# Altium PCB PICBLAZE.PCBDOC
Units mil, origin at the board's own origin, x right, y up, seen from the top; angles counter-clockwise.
Board outline 6000 x 4000 mil, 2 copper layers (Top Layer, Bottom Layer); 32 components, 76 nets, 253 pads, 144 vias.
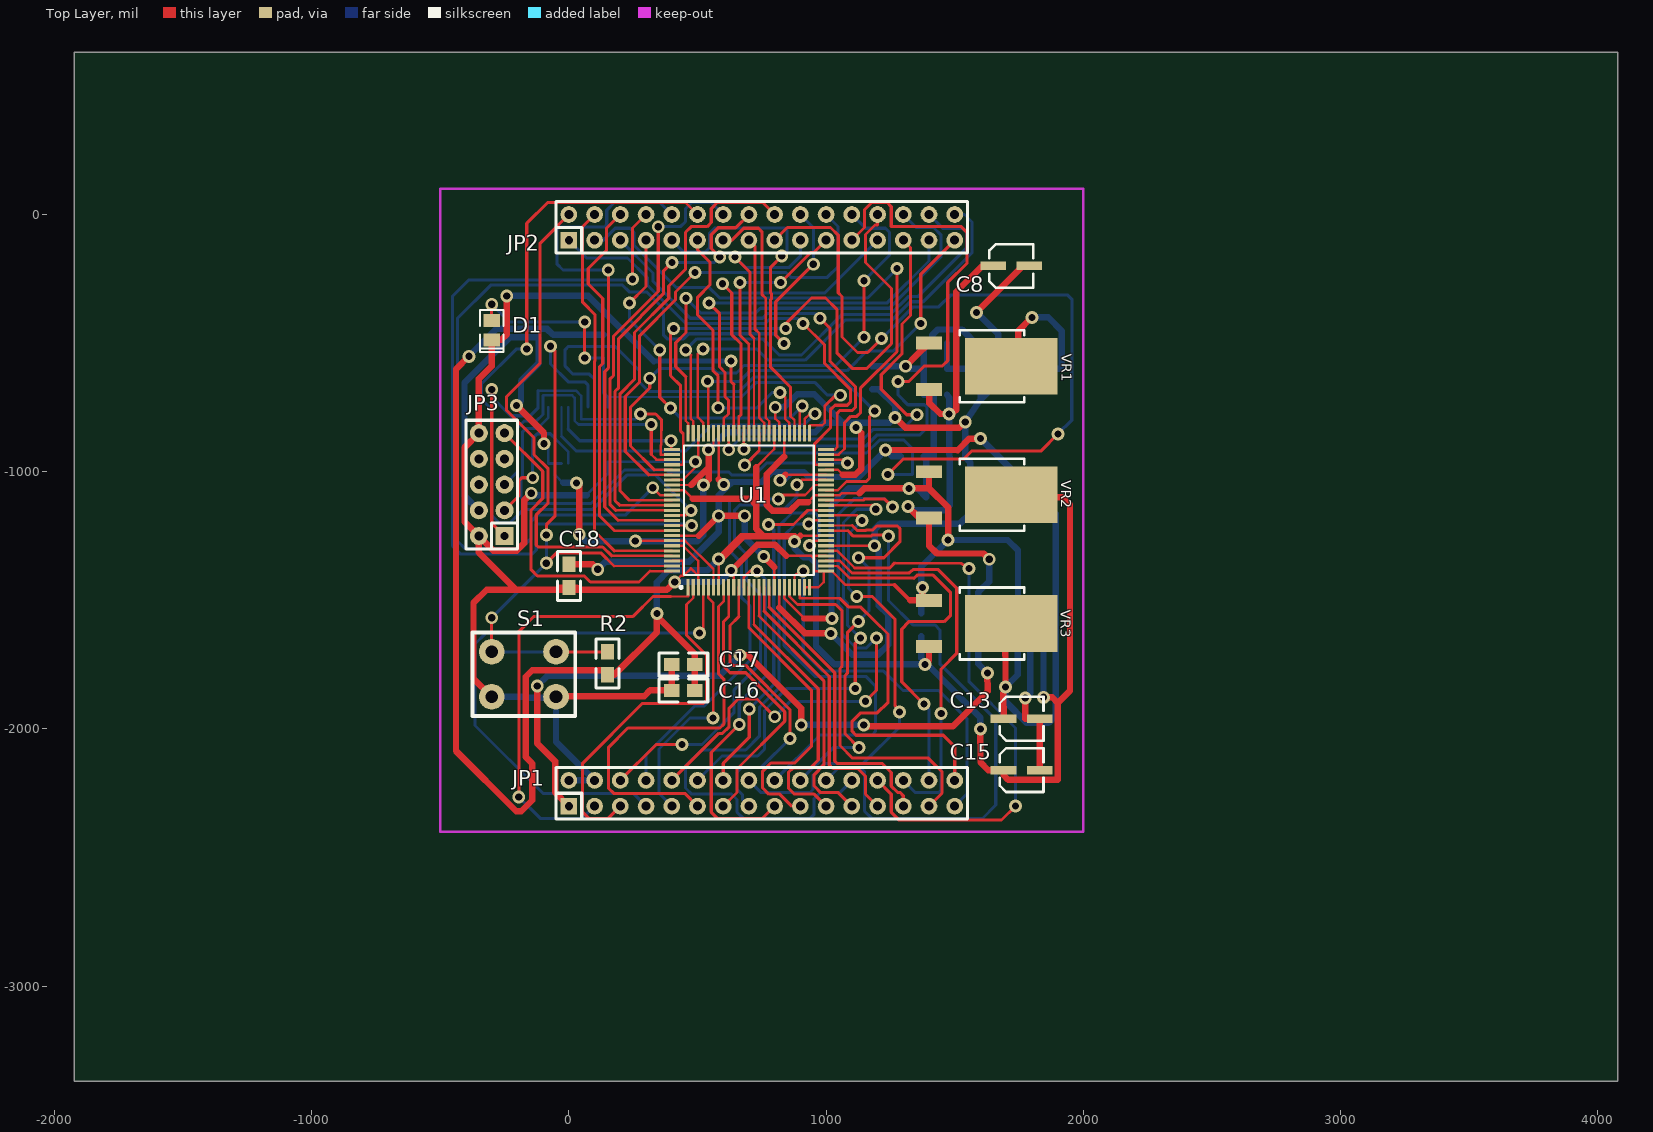
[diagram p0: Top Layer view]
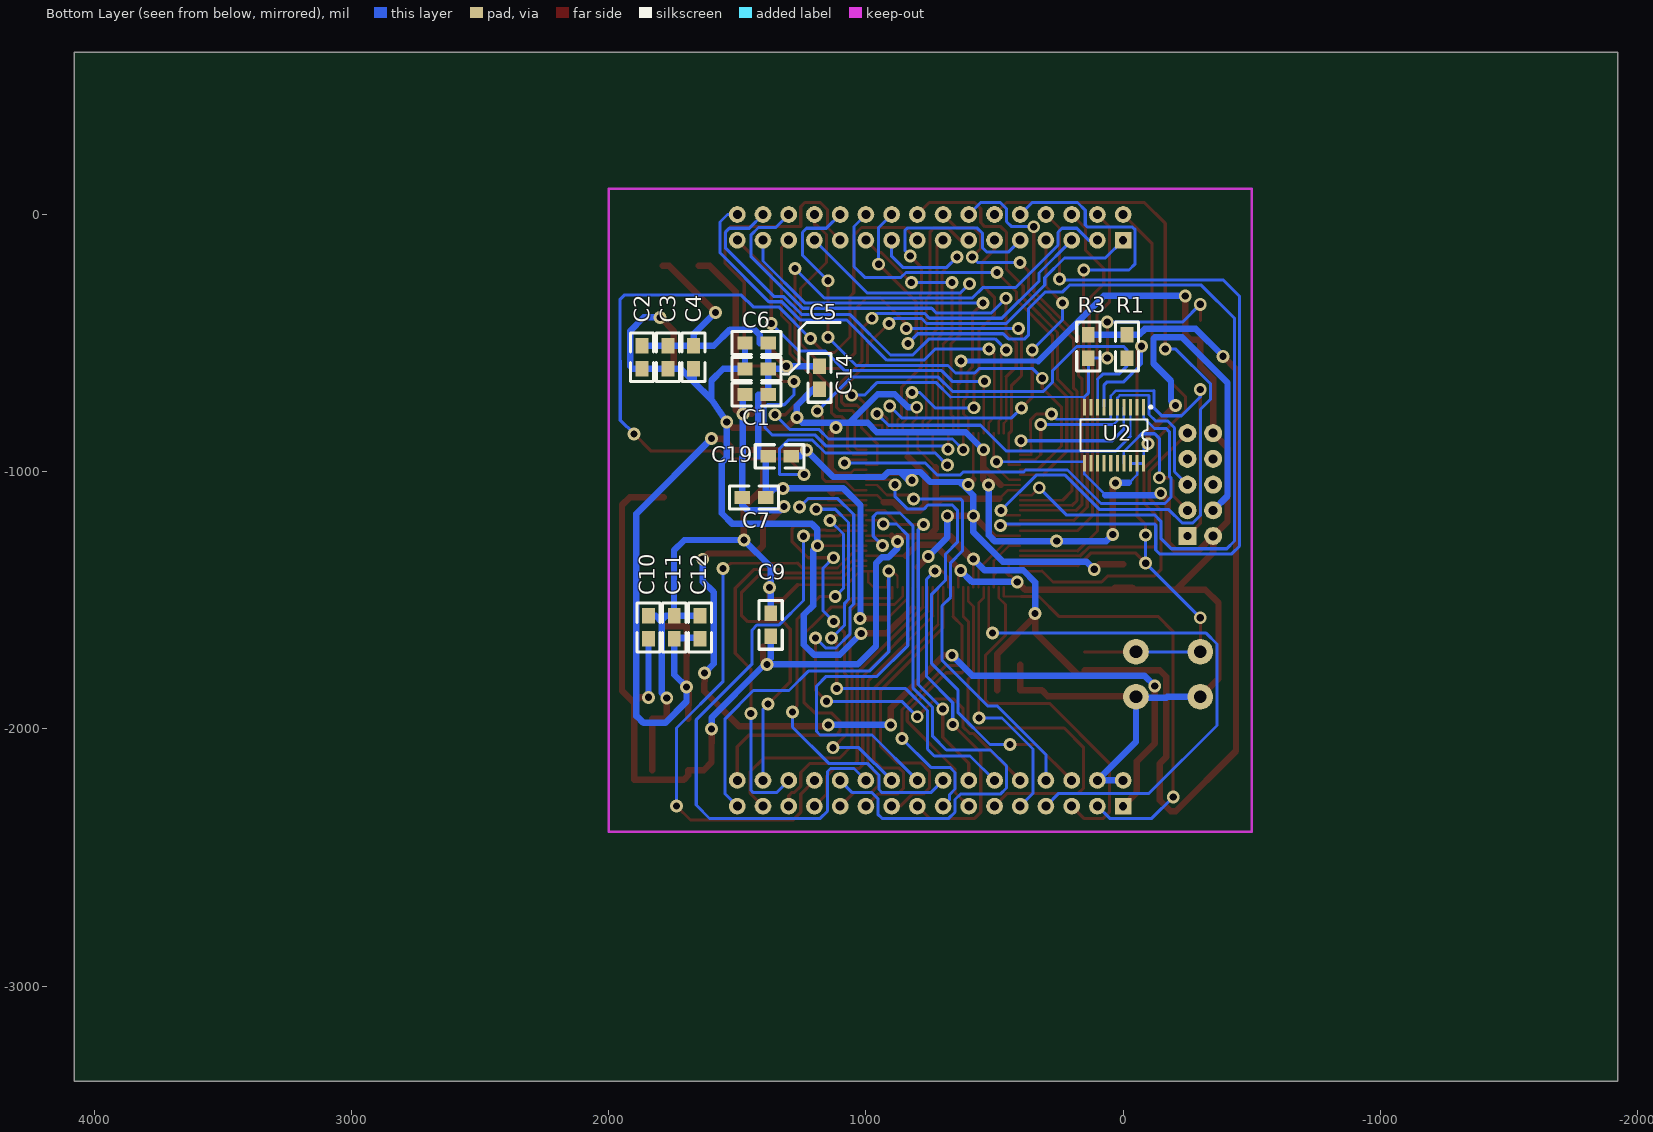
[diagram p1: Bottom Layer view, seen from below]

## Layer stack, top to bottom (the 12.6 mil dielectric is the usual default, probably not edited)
Top Layer: signal copper 1.4
Dielectric: dielectric 12.6, FR-4, Dk 4.8
Bottom Layer: signal copper 1.4

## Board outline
-1922.68,-3369.45 4077.32,-3369.45 4077.32,630.55 -1922.68,630.55

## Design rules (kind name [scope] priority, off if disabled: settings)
Clearance Clearance_1 [InComponent('U1') Or InComponent('U2')] p1: gap=7
Clearance [All] p2: gap=8
ComponentClearance [All] p1: gap=10 collisioncheckmode=0
FanoutControl Fanout_BGA [IsBGA] p1: bgadir=Out bgaviamode=Centered fanoutstyle=Auto fanoutdirection=InThenOut viagrid=1 // Fanout_BGA (Default Rule)
FanoutControl Fanout_LCC [IsLCC] p2: bgadir=Out bgaviamode=Centered fanoutstyle=Auto fanoutdirection=InThenOut viagrid=1 // Fanout_LCC (Default Rule)
FanoutControl Fanout_SOIC [IsSOIC] p3: bgadir=Out bgaviamode=Centered fanoutstyle=Auto fanoutdirection=InThenOut viagrid=1 // Fanout_SOIC (Default Rule)
FanoutControl Fanout_Small [(CompPinCount < 5)] p4: bgadir=Out bgaviamode=Centered fanoutstyle=Auto fanoutdirection=InThenOut viagrid=1 // Fanout_Small (Default Rule)
FanoutControl Fanout_Default [All] p5: bgadir=Out bgaviamode=Centered fanoutstyle=Auto fanoutdirection=InThenOut viagrid=1 // Fanout_Default (Default Rule)
PolygonConnect [All] p1: connectstyle=Relief reliefconductorwidth=10 reliefentries=4 polygonreliefangle="90 Angle"
RoutingLayers [All] p1: top layer_v5=FALSE bottom layer_v5=FALSE
RoutingVias [All] p1: holewidth=28 width=50 viastyle="Through Hole" minholewidth=28 minwidth=50 maxholewidth=28 maxwidth=50
SMDNeckDown [All] p1: percent=80.000
SolderMaskExpansion [All] p1: expansion=4
TestPointUsage [All] p1: valid=0 allowmultiple=FALSE
Testpoint [All] p1: side=15 testpointundercomponent=TRUE minsize=40 maxsize=100 preferedsize=60 minholesize=0 maxholesize=40 preferedholesize=32 testpointgrid=1 style=1023 order=1234567890
Width Width_1 [InNet('+1,2V') Or InNet('+2,5V') Or InNet('+3,3V') Or InNet('+5V') Or InNet('GND')] p1: maxlimit=25 minlimit=10 preferedwidth=25
Width [All] p2: maxlimit=12 minlimit=10 preferedwidth=12
11 further rules are at their usual default settings.

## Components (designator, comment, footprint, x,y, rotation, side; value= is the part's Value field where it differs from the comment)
C1 "Cap" 0805 1380,-700 r0 bottom
C2 "Cap" 0805 1870,-600 r90 bottom
C3 "Cap" 0805 1770,-600 r90 bottom
C4 "Cap" 0805 1670,-600 r90 bottom
C5 "Cap" 0805 1470,-600 r180 bottom
C6 "Cap Pol3" 0805 1470,-500 r180 bottom
C7 "Cap" 0805 1480,-1100 r180 bottom
C8 "Cap Pol3" CE1SMD4X5.4 1650,-200 r0 top
C9 "Cap" 0805 1370,-1550 r270 bottom
C10 "Cap" 0805 1845,-1650 r90 bottom
C11 "Cap" 0805 1745,-1650 r90 bottom
C12 "Cap" 0805 1645,-1650 r90 bottom
C13 "Cap Pol3" CE1SMD4X5.4 1690,-1960 r0 top
C14 "Cap" 0805 1180,-680 r90 bottom
C15 "Cap Pol3" CE1SMD4X5.4 1690,-2160 r0 top
C16 "Cap" 0805 400,-1850 r0 top
C17 "Cap" 0805 400,-1750 r0 top
C18 "Cap" 0805 0,-1450 r90 top
C19 "Cap" 0805 1380,-940 r180 bottom
D1 "LED3" "SMD _LED" -300,-450 r90 top
JP1 "Header 16X2" IDC-32_65mils 0,-2300 r0 top
JP2 "Header 16X2" IDC-32_65mils 0,-100 r0 top
JP3 "JTAG" IDC-10 -850,-1650 r90 top
R1 "Res2" 0805 -14.66,-558.08 r90 bottom
R2 "Res2" 0805 150,-1700 r270 top
R3 "Res2" 0805 135.34,-558.08 r90 bottom
S1 "SW-PB" U_SW -50,-1700 r270 top
U1 "XC3S200-4VQ100C" VQ100 700,-1150 r90 top
U2 "XCF01SVO20C" VO20 35.34,-858.08 r0 bottom
VR1 "Comment" TO252_mod 1400,-500 r270 top
VR2 "Comment" TO252_mod 1400,-1000 r270 top
VR3 "Comment" TO252_mod 1400,-1500 r270 top locked

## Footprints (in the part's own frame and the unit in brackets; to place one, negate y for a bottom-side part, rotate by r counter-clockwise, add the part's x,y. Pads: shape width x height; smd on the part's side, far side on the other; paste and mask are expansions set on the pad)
0805 [mil]
  rect 60x50 smd: 1(0,0) 2(90,0)
  silkscreen extent -50,-45 140,45
CE1SMD4X5.4 [mil]
  rect 100x33 smd: 1(0,0) 2(140,0)
  silkscreen extent -15,-85 155,85
IDC-10 [mil]
  rect 70x70 hole 32: 1(400,-600)
  round 70 hole 35: 2(400,-500) 3(500,-600) 4(500,-500) 5(600,-600) 6(600,-500) 7(700,-600) 8(700,-500) 9(800,-600) 10(800,-500)
  silkscreen extent 350,-650 850,-450
IDC-32_65mils [mil]
  rect 65x65 hole 32: 1(0,0)
  round 65 hole 35: 2(0,100) 3(100,0) 4(100,100) 5(200,0) 6(200,100) 7(300,0) 8(300,100) 9(400,0) 10(400,100) 11(500,0) 12(500,100) 13(600,0) 14(600,100) 15(700,0) 16(700,100) 17(800,0) 18(800,100) 19(900,0) 20(900,100) 21(1000,0) 22(1000,100) 23(1100,0) 24(1100,100) 25(1200,0) 26(1200,100) 27(1300,0) 28(1300,100) 29(1400,0) 30(1400,100) 31(1500,0) 32(1500,100)
  silkscreen extent -50,-50 1550,150
"SMD _LED" [mm]
  rect 1.3x1.6 smd: 1(0.95,0) 2(-0.95,0)
  silkscreen extent -2.13,-1.15 2,1.15
TO252_mod [mil]
  rect 50x100 smd: 1(0,0) 3(180,0)
  rect 220x360 smd: 2(90,320)
  silkscreen extent -50,120 230,370
U_SW [mil]
  round 100 hole 50: 1(175,0) 1(175,-250) 2(0,0) 2(0,-250)
  silkscreen extent -75,-325 250,75
VO20 [mm]
  rect 0.3x1.65 smd: 1(-2.925,-2.775) 2(-2.275,-2.775) 3(-1.625,-2.775) 4(-0.975,-2.775) 5(-0.325,-2.775) 6(0.325,-2.775) 7(0.975,-2.775) 8(1.625,-2.775) 9(2.275,-2.775) 10(2.925,-2.775) 11(2.925,2.775) 12(2.275,2.775) 13(1.625,2.775) 14(0.975,2.775) 15(0.325,2.775) 16(-0.325,2.775) 17(-0.975,2.775) 18(-1.625,2.775) 19(-2.275,2.775) 20(-2.925,2.775)
  silkscreen extent -3.75,-2.9 3.3,1.55
VQ100 [mm]
  rect 1.6x0.3 smd: 1(-7.6,6) 2(-7.6,5.5) 3(-7.6,5) 4(-7.6,4.5) 5(-7.6,4) 6(-7.6,3.5) 7(-7.6,3) 8(-7.6,2.5) 9(-7.6,2) 10(-7.6,1.5) 11(-7.6,1) 12(-7.6,0.5) 13(-7.6,0) 14(-7.6,-0.5) 15(-7.6,-1) 16(-7.6,-1.5) 17(-7.6,-2) 18(-7.6,-2.5) 19(-7.6,-3) 20(-7.6,-3.5) 21(-7.6,-4) 22(-7.6,-4.5) 23(-7.6,-5) 24(-7.6,-5.5) 25(-7.6,-6) 51(7.6,-6) 52(7.6,-5.5) 53(7.6,-5) 54(7.6,-4.5) 55(7.6,-4) 56(7.6,-3.5) 57(7.6,-3) 58(7.6,-2.5) 59(7.6,-2) 60(7.6,-1.5) 61(7.6,-1) 62(7.6,-0.5) 63(7.6,0) 64(7.6,0.5) 65(7.6,1) 66(7.6,1.5) 67(7.6,2) 68(7.6,2.5) 69(7.6,3) 70(7.6,3.5) 71(7.6,4) 72(7.6,4.5) 73(7.6,5) 74(7.6,5.5) 75(7.6,6)
  rect 0.3x1.6 smd: 26(-6,-7.6) 27(-5.5,-7.6) 28(-5,-7.6) 29(-4.5,-7.6) 30(-4,-7.6) 31(-3.5,-7.6) 32(-3,-7.6) 33(-2.5,-7.6) 34(-2,-7.6) 35(-1.5,-7.6) 36(-1,-7.6) 37(-0.5,-7.6) 38(0,-7.6) 39(0.5,-7.6) 40(1,-7.6) 41(1.5,-7.6) 42(2,-7.6) 43(2.5,-7.6) 44(3,-7.6) 45(3.5,-7.6) 46(4,-7.6) 47(4.5,-7.6) 48(5,-7.6) 49(5.5,-7.6) 50(6,-7.6) 76(6,7.6) 77(5.5,7.6) 78(5,7.6) 79(4.5,7.6) 80(4,7.6) 81(3.5,7.6) 82(3,7.6) 83(2.5,7.6) 84(2,7.6) 85(1.5,7.6) 86(1,7.6) 87(0.5,7.6) 88(0,7.6) 89(-0.5,7.6) 90(-1,7.6) 91(-1.5,7.6) 92(-2,7.6) 93(-2.5,7.6) 94(-3,7.6) 95(-3.5,7.6) 96(-4,7.6) 97(-4.5,7.6) 98(-5,7.6) 99(-5.5,7.6) 100(-6,7.6)
  silkscreen extent -7.72,-6.4 6.4,6.82

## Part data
C1 C2 C3 C4 C5 C7 C9 C10 C11 C12 C14 C16 C17 C18 C19: "Capacitor"
C6 C8 C13 C15: "Polarized Capacitor (Surface Mount)"
D1: "Typical BLUE SiC LED"
JP1 JP2: "Header, 16-Pin, Dual row"
JP3: library part "Header 5X2", "Header, 5-Pin, Dual row"
R1 R2 R3: "Resistor"
S1: "Switch"
U1: "Spartan-3 1.2V FPGA, 63 User I/Os, 100-pin VQFP, Standard Performance, Commercial Grade"
U2: "XCF00S Series, Platform Flash In-System Programmable Configuration 3.3V PROM, 20-Pin TSOP, 1-Megabit, Commercial Grade"

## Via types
v1: diameter 50, hole 28, Top Layer to Bottom Layer, 144 vias

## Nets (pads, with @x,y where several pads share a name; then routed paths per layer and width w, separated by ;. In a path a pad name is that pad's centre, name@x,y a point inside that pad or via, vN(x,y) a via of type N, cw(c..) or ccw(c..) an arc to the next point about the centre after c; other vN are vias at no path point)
+1,2V: C11.1 C12.1 C13.1 C18.2 C19.2 U1.18 U1.45 U1.69 U1.93 VR3.2 | length 5481.7
  Top Layer w9.45: U1.93 505.35,-1248.42 ; 581.89,-1029.52 U1.69 ; U1.18 798.42,-1370.55 ; 842.07,-1012.2 U1.45
  Top Layer w25: C18.2 92.87,-1360 v1(112.32,-1379.45) ; 505.35,-1248.42 v1(582.32,-1171.45) v1(683.32,-1171.45) ; 581.89,-1029.52 v1(602.32,-1049.95) ; v1(757.32,-1329.45) 798.42,-1370.55 ; v1(821.11,-1033.16) 842.07,-1012.2 ; v1(1231.32,-915.45) 1511.32,-916.45 1556,-871 v1(1600,-871) ; C13.1 1689,-1861 v1(1697.32,-1836.45) 1697,-1600 VR3.2@1786.54,-1600
  Bottom Layer w25: v1(112.32,-1379.45) 142.32,-1349.45 467.3,-1349.45 582.32,-1234.42 v1(582.32,-1171.45) 582.32,-1091.45 613.07,-1060.7 633.82,-1039.95 ; v1(602.32,-1049.95) 612.32,-1039.95 633.82,-1039.95 ; v1(683.32,-1171.45) 683.32,-1255.45 v1(757.32,-1329.45) ; v1(821.11,-1033.16) 827.89,-1039.95 866.89,-1000.95 ; C19.2 1255.87,-940 v1(1231.32,-915.45) 1126.32,-1020.45 932.82,-1020.45 913.32,-1000.95 866.89,-1000.95 ; v1(1600,-871) 1892,-1163 1892,-1951 ; 1891.32,-1949.45 1864.32,-1976.45 1780.32,-1976.45 1697.32,-1893.45 v1(1697.32,-1836.45) 1745,-1789 C11.1 ; 633.82,-1039.95 749.89,-1039.95 788.89,-1000.95 821.11,-1000.95 866.89,-1000.95 ; C11.1 1645,-1645.77 1745,-1645.77 C11.1
+2,5V: C9.2 C10.1 C15.1 C16.2 C17.2 R1.2 R2.2 R3.2 U1.7 U1.33 U1.58 U1.84 VR2.2 VR3.3 | length 9479.3
  Top Layer w9.45: U1.84 448.13,-1071.26 482.32,-1105.45 ; U1.7 v1@581.89,-1349.45 ; 728.82,-981.87 798.43,-912.26 U1.58 ; 899.84,-1248.43 U1.33
  Top Layer w25: v1(-388.68,-551.45) -438.68,-601.45 -438.68,-2085.45 -204.68,-2319.45 -184.68,-2319.45 -142.68,-2277.45 -142.68,-2134.45 -168.18,-2108.95 -168.18,-1796.95 -142.68,-1771.45 150,-1771.45 R2.2 175.77,-1790 342.32,-1623.45 v1(342.32,-1551.45) ; v1@342.32,-1561.77 490,-1709.45 C17.2 C16.2 ; 482.32,-1105.45 704.82,-1105.45 728.82,-1129.45 ; v1@581.89,-1349.45 680.39,-1250.95 ; v1(582.32,-1339.45) 670.82,-1250.95 877.32,-1250.95 v1(877.32,-1270.95) ; 728.82,-981.87 728.82,-1222.45 757.32,-1250.95 ; 857.32,-1250.95 v1(877.32,-1270.95) ; 899.84,-1248.43 v1(877.32,-1270.95) ; v1(1385,-1748.95) 1400,-1733.95 VR3.3 ; v1(1600,-2000) 1600.32,-2116.95 1600.32,-2129.45 1630.87,-2160 C15.1 1690,-2180.12 1707.32,-2197.45 1901.32,-2197.45 1901.32,-1922.45 1901,-1899 ; VR2.2@1786.54,-1100 1918,-1100 1948,-1129 1948,-1852 1901,-1899 ; v1(1845,-1877) 1879,-1877 1901,-1899
  Bottom Layer w25: v1(-388.68,-551.45) -282.18,-444.95 -84.7,-444.95 -61.57,-468.08 R1.2 R3.2 ; v1(342.32,-1551.45) 342.32,-1429.45 388.82,-1382.95 538.82,-1382.95 v1(582.32,-1339.45) ; v1(877.32,-1270.95) 877.32,-1296.95 912.32,-1331.95 937.32,-1331.95 960.82,-1355.45 960.82,-1678.95 1030.82,-1748.95 v1@1393.82,-1748.95 ; C9.2 1370,-1725.13 1412.32,-1767.45 1600,-1956 v1(1600,-2000) ; v1(1845,-1877) C10.1
+3,3V: C2.1 C3.1 C4.1 C5.1 C6.1 C14.1 JP3.4 U1.6 U1.19 U1.31 U1.46 U1.57 U1.70 U1.83 U1.94 U2.18 U2.19 U2.20 VR1.2 | length 8726.3
  Top Layer w9.45: v1@259.66,-1268.11 U1.94 451.98,-1268.11 562.2,-1378.33 U1.6 ; U1.83 475.33,-1051.57 ; v1(543.32,-914.45) 562.2,-895.57 U1.70 ; v1(802.32,-749.45) 802.32,-793.45 818.11,-809.24 U1.57 ; 818.11,-1528.83 U1.19 ; U1.31 v1(1188.32,-1287.8) ; U1.46 1045.6,-992.52 1065.02,-1011.95
  Top Layer w25: v1(-203.68,-742.45) -96.68,-849.45 v1(-96.68,-891.45) ; v1(29.32,-1043.45) 40.32,-1054.45 v1(40.32,-1244.45) ; v1(258.32,-1269.45) v1@259.66,-1268.11 ; 475.33,-1051.57 499.08,-1027.83 543.32,-983.58 ; v1(522.82,-1051.57) 543.32,-1031.07 543.32,-983.58 ; v1(543.32,-914.45) 543.32,-983.58 ; 818.11,-1528.83 917.75,-1628.47 v1(1018.34,-1628.47) ; 1065.02,-1011.95 1113.82,-1011.95 1136.32,-989.45 1136.32,-848.45 v1(1116.32,-828.45) ; v1(1268.32,-789.45) 1308.32,-829.45 1518,-829 v1(1541,-807) ; VR1.2@1747.2,-588.42 1747,-453 v1(1800,-400)
  Bottom Layer w9.45: v1(-96.68,-891.45) -79.82,-908.31 U2.20 ; U2.19 -54.23,-1011.9 -22.68,-1043.45
  Bottom Layer w12: U2.20 U2.19 U2.18
  Bottom Layer w25: JP3.4 -405.68,-1094.32 -405.68,-654.28 -229.35,-477.95 -122.68,-477.95 -118.16,-482.46 -118.16,-579.56 -186.18,-647.58 -186.18,-724.95 v1(-203.68,-742.45) ; -22.68,-1043.45 v1(29.32,-1043.45) ; v1(40.32,-1244.45) 65.32,-1269.45 v1(258.32,-1269.45) 499.65,-1269.45 522.82,-1246.28 v1(522.82,-1051.57) ; v1(543.32,-914.45) 611.82,-845.95 957.32,-845.95 993.32,-809.95 1064.82,-809.95 ; v1(802.32,-749.45) 836.32,-749.45 887.32,-698.45 953.32,-698.45 1064.82,-809.95 ; v1(1018.34,-1628.47) 1101.82,-1711.95 1201.82,-1711.95 1241.32,-1672.45 1241.32,-1556.45 1205.32,-1520.45 1205.32,-1304.8 v1(1188.32,-1287.8) 1188.32,-1224.45 1209.82,-1202.95 1519,-1203 1560,-1161 1560,-965 ; v1(1116.32,-828.45) 1134.82,-809.95 ; C14.1 1205.37,-680 1268.32,-742.95 v1(1268.32,-789.45) 1247.82,-809.95 1134.82,-809.95 ; C6.1 C5.1 1554.87,-600 1600.32,-645.45 1600.32,-719.45 ; 1560,-964 1540.94,-944.06 v1(1541,-807) 1600.32,-719.45 ; C4.1 1670,-649.77 ; v1(1800,-400) 1863,-400 1916,-453 1916.32,-589.45 1905.77,-600 C2.1 C3.1 1719.77,-600 1694.89,-624.89 1670,-649.77 ; 1064.82,-809.95 1116.32,-809.95 1134.82,-809.95 ; 1600.32,-719.45 1670,-649.77
+5V: C1.2 C7.1 C8.1 JP1.1 VR1.3 VR2.3 | length 5002.4
  Top Layer w25: v1(-122.68,-1832.45) -122.68,-2056.45 -53.68,-2125.45 -53.68,-2246.32 JP1.1 ; v1(665.32,-1713.45) 696.84,-1713.45 903.32,-1919.93 v1(903.32,-1984.45) ; v1(1146.32,-1984.45) 1151.32,-1989.45 1493.32,-1989.45 1628,-1854 v1(1627,-1783) ; v1(1317.82,-1134.95) 1363,-1180 VR2.3 1400,-1288 1431,-1318 1612,-1318 v1(1634,-1340) ; VR1.3 1401,-733 1444,-775 v1(1478,-776) 1506,-760 1506,-300 1606.82,-200 C8.1
  Bottom Layer w25: v1(-122.68,-1832.45) -82.68,-1792.45 586.32,-1792.45 v1(665.32,-1713.45) ; v1(903.32,-1984.45) v1(1146.32,-1984.45) ; v1(1317.82,-1134.95) 1333.32,-1150.45 1459.32,-1150.45 1480,-1129.77 ; C1.2 1479,-713 v1(1478,-776) C7.1 ; v1(1627,-1783) 1591,-1746 1591,-1468 1634,-1427 v1(1634,-1340) ; 1480,-1129.77 C7.1 ; 1480,-1129.77 1480.32,-1129.45 1480.32,-1100 C7.1
DATA_CNF: U1.48 U2.1 | length 1871.5
  Top Layer w9.45: U1.48 v1@1070.02,-953.15
  Top Layer w12: v1@1070.02,-953.15 v1(1083.32,-966.45)
  Bottom Layer w9.45: -121.82,-831.45 -79.82,-789.45 U2.1
  Bottom Layer w12: -121.82,-831.45 -166.68,-831.45 -179.68,-844.45 -179.68,-1017.45 -185.68,-1023.45 -185.68,-1100.45 -162.68,-1123.45 86.32,-1123.45 216.32,-993.45 379.32,-993.45 387.32,-1001.45 622.32,-1001.45 634.32,-1013.45 721.32,-1013.45 768.32,-966.45 v1(1083.32,-966.45)
GND: C1.1 C2.2 C3.2 C4.2 C5.2 C6.2 C7.2 C8.2 C9.1 C10.2 C11.2 C12.2 C13.2 C14.2 C15.2 C16.1 C17.1 C18.1 C19.1 D1.2 JP1.2 JP1.4 JP3.2 JP3.10 S1.1 U1.3 U1.10 U1.20 U1.24 U1.25 U1.26 U1.29 U1.41 U1.56 U1.66 U1.73 U1.82 U1.95 U1.98 U2.11 VR1.1 VR2.1 VR3.1 | length 14724.3
  Top Layer w9.45: U1.98 445.32,-1346.85 445.32,-1404.45 ; U1.95 444.32,-1287.8 503.15,-1346.62 503.15,-1404.45 ; U1.82 442.88,-1031.89 503.15,-971.62 503.15,-960.95 U1.73 ; v1(411.32,-1428.45) 435.32,-1404.45 445.32,-1404.45 ; U1.3 503.15,-1404.45 ; U1.10 640.94,-1384.45 v1@640.94,-1374.83 ; U1.66 641,-660 ; U1.20 837.8,-1492.92 915.32,-1570.45 ; 837.8,-940.97 U1.56 ; 844.65,-1327.17 942.27,-1327.17 954.55,-1339.45 ; U1.24@916.54,-1423.44 U1.24 916.54,-1449.45 936.22,-1449.45 U1.25 970,-1449 991,-1429 U1.26@991.32,-1386.22 ; 929.82,-1118.45 957.32,-1090.94 U1.41 1053.2,-1090.94 1059.7,-1084.45 1129.32,-1084.45 ; U1.29 954.55,-1327.17 954.55,-1339.45 ; 1266.54,-1439.95 1075.82,-1439.95 1022.09,-1386.22 U1.26 U1.26@991.32,-1386.22 ; 445.32,-1404.45 474.24,-1375.53 503.15,-1404.45 ; 954.55,-1339.45 954.55,-1386.22 U1.26@991.32,-1386.22
  Top Layer w12: v1(492.48,-960.95) v1@503.15,-971.62 ; v1(630,-570) 630,-650 641,-660
  Top Layer w15: 1266.54,-1439.95 1326.59,-1500
  Top Layer w25: S1.1@-300,-1875 -370.68,-1804.32 -370.68,-1509.45 -319.68,-1458.45 -205.34,-1458.45 ; v1(-241.68,-316.45) -241.68,-466.4 -262.68,-487.4 D1.2 -300,-589.34 -350,-639.34 JP3.10 -405.68,-905.68 -405.68,-1194.32 JP3.2 ; v1(-146.18,-1083.7) -174.12,-1111.64 -174.12,-1277.89 -202.68,-1306.45 -293.55,-1306.45 JP3.2 ; S1.1@-50,-1875 -12.5,-1875 -12.5,-1872.45 293.13,-1872.45 315.58,-1850 C16.1 C17.1 ; v1(411.32,-1428.45) 381.32,-1458.45 38.32,-1458.45 ; v1(631.32,-1384.45) 640.94,-1374.83 731.82,-1283.95 801.43,-1283.95 844.65,-1327.17 ; 837.8,-940.97 768.82,-1009.95 768.82,-1129.45 791.32,-1151.95 859.82,-1151.95 893.32,-1118.45 929.82,-1118.45 ; 915.32,-1570.45 v1(1023.32,-1570.45) ; 1129.32,-1084.45 1148.82,-1064.95 v1(1322,-1065) 1400,-1065 ; v1(1309.32,-590) 1350.85,-548.48 VR1.1 ; 1326.59,-1500 1353.46,-1500 1374.32,-1500 v1(1374.32,-1450.61) ; VR2.1 1400,-1065 ; v1(1474.32,-1265.45) 1475,-1139 1400,-1065 ; v1(1584.32,-380.45) 1764.77,-200 C8.2 ; v1(1774.32,-1879.45) 1774.32,-1960 C13.2 C15.2 ; JP3.2 -350,-1313.78 -205.34,-1458.45 ; -205.34,-1458.45 -42.68,-1458.45 ; -42.68,-1458.45 -34.23,-1450 C18.1 29.87,-1450 38.32,-1458.45 ; -42.68,-1458.45 0,-1458.45 38.32,-1458.45
  Bottom Layer w9.45: 69,-1090.95 150.5,-1009.45 U2.11 150.5,-960.95 v1(492.48,-960.95)
  Bottom Layer w20: 330,-570 v1(630,-570)
  Bottom Layer w25: S1.1@-300,-1875 -171.13,-1875 -168.18,-1877.95 -52.95,-1877.95 -50,-1875 -50,-2050 JP1.4 JP1.2 ; v1(-241.68,-316.45) 74.82,-316.45 330,-570 ; v1(-146.18,-1083.7) -138.93,-1090.95 69,-1090.95 ; v1(411.32,-1428.45) 587.32,-1428.45 v1(631.32,-1384.45) ; v1(1023.32,-1570.45) 1020.82,-1567.95 1020.82,-1130.45 1087.32,-1064.95 1361.82,-1064.95 1357.89,-1067.88 C7.2 ; C14.2 v1(1309.32,-590) 1319.32,-600 C5.2 ; C9.1 1370,-1369.77 v1(1474.32,-1265.45) 1706,-1266 1746,-1305 1746,-1561 C11.2 ; 1390,-1035.77 C7.2 ; v1(1584.32,-380.45) 1670,-466.13 C4.2 ; C12.2 1777.32,-1560 ; v1(1774.32,-1879.45) 1794.32,-1859.45 1794.32,-1577 ; 1777,-1560 1794,-1577 ; 1794.32,-1583 1817.32,-1560 C10.2 ; C2.2 C3.2 C4.2 ; C5.2 C6.2 1411.82,-500 1411.82,-469.45 1434.32,-446.95 1528.27,-446.95 1591.32,-510 C4.2 ; C5.2 1380,-650.45 C1.1 1418.82,-700 1418.82,-940 C19.1 1389,-958 C7.2
INIT_B: R1.1 U1.42 U2.8 | length 2149.9
  Top Layer w9.45: U1.42 1046.32,-1071.26 1079.13,-1038.45
  Top Layer w12: 1079.13,-1038.45 1154.9,-1038.45 1168.57,-1024.77 1168.57,-785.2 v1(1189.32,-764.45)
  Bottom Layer w9.45: U2.8 99.32,-640.45
  Bottom Layer w12: 99.32,-640.45 79.32,-620.45 16.34,-620.45 -14.66,-589.45 R1.1 -14.66,-525.43 -2.68,-513.45 180.32,-513.45 275.32,-608.45 275.32,-653.45 309.32,-687.45 663.27,-687.45 718.27,-632.45 1057.32,-632.45 v1(1189.32,-764.45)
NetD1_1: D1.1 R3.1 U1.51 U2.10 | length 2050
  Top Layer w9.45: U1.51 936.22,-819.51 984.98,-819.51 995.05,-809.45 995.05,-744.72
  Top Layer w12: D1.1 v1(-300,-349.21) ; v1(61.49,-558.08) v1(61.49,-418.45) ; 995.05,-744.72 1037.32,-702.45 v1(1055.32,-702.45)
  Bottom Layer w9.45: U2.10 150.5,-709.45 671.32,-709.45
  Bottom Layer w12: v1(-300,-349.21) -230.76,-418.45 v1(61.49,-418.45) ; v1(61.49,-558.08) R3.1 135.34,-694.29 150.5,-709.45 ; 671.32,-709.45 728.32,-652.45 955.32,-652.45 1005.32,-702.45 v1(1055.32,-702.45)
NetJP3_1: JP3.1 U1.77 U2.6 | length 1685.7
  Top Layer w9.45: 359.32,-840.45 359.32,-894.39 357.44,-896.27 357.44,-933.46 U1.77
  Top Layer w12: v1(-299.68,-680.45) -299.68,-1200.32 JP3.1 ; v1(278.32,-775.45) 337.32,-775.45 359.32,-797.45 359.32,-840.45
  Bottom Layer w9.45: -120.68,-684.45 27.32,-684.45 48.14,-705.26 U2.6 48.14,-795.45 258.32,-795.45
  Bottom Layer w12: v1(-299.68,-680.45) -299.68,-709.45 -226.71,-782.41 -149.64,-782.41 -120.68,-753.45 -120.68,-684.45 ; 258.32,-795.45 v1(278.32,-775.45)
NetJP3_3: JP3.3 U2.17 | length 568.9
  Top Layer w12: JP3.3 -193.68,-1093.68 -193.68,-1034.45 -182.68,-1023.45 v1(-140.68,-1023.45)
  Bottom Layer w9.45: -47.85,-876.72 -3.05,-921.52 U2.17
  Bottom Layer w12: v1(-140.68,-1023.45) -140.68,-870.45 -122.68,-852.45 -72.12,-852.45 -47.85,-876.72
NetJP3_5: JP3.5 U1.78 U2.5 | length 1161.3
  Top Layer w9.45: 320.32,-933.48 339.99,-953.15 U1.78
  Top Layer w12: 320.32,-933.48 v1(320.32,-816.45)
  Bottom Layer w9.45: -100.35,-703.45 13.21,-703.45 22.54,-712.78 U2.5 22.54,-801.67 37.32,-816.45
  Bottom Layer w12: JP3.5 -199.68,-999.68 -199.68,-829.45 -172.64,-802.41 -125.54,-802.41 -100.35,-777.22 -100.35,-703.45 ; 37.32,-816.45 v1(320.32,-816.45)
NetJP3_9: JP3.9 U1.100 | length 1196.1
  Top Layer w9.45: 315.1,-1386.22 U1.100
  Top Layer w12: JP3.9 -101.5,-998.5 -101.5,-1103.27 -146.68,-1148.45 -146.68,-1381.45 -122.68,-1405.45 60.32,-1405.45 83.32,-1428.45 272.87,-1428.45 315.1,-1386.22
NetR2_1: R2.1 S1.2 U1.99 U2.7 | length 2606.7
  Top Layer w9.45: 175.41,-1366.54 U1.99
  Top Layer w12: S1.2@-300,-1700 v1(-300,-1567.77) ; v1(-87.68,-1355.45) -47.68,-1315.45 124.32,-1315.45 175.41,-1366.54 ; v1(-87.68,-1246.45) -87.68,-1206.45 -54.68,-1173.45 -54.68,-529.45 v1(-71.68,-512.45) ; S1.2@-50,-1700 R2.1
  Bottom Layer w12: S1.2@-300,-1700 S1.2@-50,-1700 ; v1(-300,-1567.77) v1(-87.68,-1355.45) v1(-87.68,-1246.45) ; v1(-71.68,-512.45) -71.68,-581.45 -2.68,-650.45 61.73,-650.45 73.73,-662.45 U2.7
NetU1_52: U1.52 U2.3 | length 1288.2
  Top Layer w9.45: U1.52 916.54,-795.23 v1@937.32,-774.45
  Top Layer w12: v1@937.32,-774.45 v1(957.32,-774.45)
  Bottom Layer w9.45: -28.64,-862.45 U2.3
  Bottom Layer w12: -28.64,-862.45 28.36,-919.45 454.32,-919.45 554.32,-819.45 912.32,-819.45 v1(957.32,-774.45)
NetU1_76: U1.76 U2.4 | length 542.5
  Top Layer w9.45: v1(397.32,-879.47) 397.32,-913.78 U1.76
  Bottom Layer w9.45: -3.05,-834.52 U2.4
  Bottom Layer w12: -3.05,-834.52 41.9,-879.47 v1(397.32,-879.47)
P1: JP1.3 U1.1 | length 1742.4
  Top Layer w9.45: 397.1,-1484.95 463.78,-1484.95 U1.1
  Top Layer w12: v1(-194.68,-2264.45) -194.68,-1621.45 -135.68,-1562.45 249.82,-1562.45 327.32,-1484.95 397.1,-1484.95
  Bottom Layer w12: v1(-194.68,-2264.45) -111.68,-2347.45 52.55,-2347.45 JP1.3
P2: JP1.5 U1.2 | length 1431.3
  Top Layer w9.45: 457.32,-1516.45 483.46,-1490.31 U1.2
  Top Layer w12: JP1.5 152.55,-2347.45 77.32,-2347.45 53.32,-2323.45 53.32,-2133.45 286.32,-1900.45 523.32,-1900.45 534.32,-1889.45 534.32,-1712.54 457.32,-1635.54 457.32,-1516.45
P4: JP1.7 U1.4 | length 2185.6
  Top Layer w9.45: v1@522.83,-1611.94 U1.4
  Top Layer w12: v1(507.32,-1627.45) v1@522.83,-1611.94
  Bottom Layer w12: JP1.7 250.45,-2250.45 -100.68,-2250.45 -364.68,-1986.45 -364.68,-1669.45 -322.68,-1627.45 v1(507.32,-1627.45)
P5: JP1.9 U1.5 | length 1018.7
  Top Layer w9.45: U1.5 542.52,-1490.24 560.62,-1508.34 v1(560.62,-1957.45)
  Bottom Layer w12: JP1.9 350.32,-2250.32 350.32,-2077.73 470.61,-1957.45 v1(560.62,-1957.45)
P8: JP1.11 U1.8 | length 1568.4
  Top Layer w9.45: 581.89,-1523.9 601.57,-1504.22 U1.8
  Top Layer w12: JP1.11 450.45,-2250.45 174.32,-2250.45 153.32,-2229.45 153.32,-2072.45 229.32,-1996.45 587.32,-1996.45 602.32,-1981.45 602.32,-1806.15 581.89,-1785.72 581.89,-1523.9
P9: JP1.13 U1.9 | length 1092.1
  Top Layer w9.45: 621.26,-1562.6 U1.9
  Top Layer w12: JP1.13 653.32,-2246.68 653.32,-2155.45 839.32,-1969.45 839.32,-1933.34 687.58,-1781.6 626.44,-1781.6 601.89,-1757.05 601.89,-1581.97 621.26,-1562.6
P11: JP1.15 U1.11 | length 1138.6
  Top Layer w9.45: 660.63,-1563.23 U1.11
  Top Layer w12: 660.63,-1563.23 626.32,-1597.54 626.32,-1741.76 637.32,-1752.76 687.03,-1752.76 859.32,-1925.06 v1(859.32,-2037.45)
  Bottom Layer w12: JP1.15 674.43,-2274.43 674.43,-2254.61 653.32,-2233.5 653.32,-2169.45 673.32,-2149.45 747.32,-2149.45 v1(859.32,-2037.45)
P12: JP1.17 U1.12 | length 1416.1
  Top Layer w9.45: U1.12 680.31,-1409.45 704.31,-1385.45
  Top Layer w12: v1(662.32,-1982.45) 553.32,-2091.45 553.32,-2323.45 577.32,-2347.45 752.55,-2347.45 JP1.17 ; 704.31,-1385.45 v1(731.32,-1385.45)
  Bottom Layer w12: v1(662.32,-1982.45) 662.32,-1897.64 764.32,-1795.64 764.32,-1418.45 v1(731.32,-1385.45)
P13: JP1.19 U1.13 | length 1189.5
  Top Layer w9.45: 700,-1606.53 U1.13
  Top Layer w12: 700,-1606.53 942.71,-1849.24 942.71,-2067.9 878.16,-2132.45 785.32,-2132.45 753.32,-2164.45 753.32,-2229.45 777.32,-2253.45 820.32,-2253.45 866.87,-2300 JP1.19
P14: JP1.21 U1.14 | length 1147.1
  Top Layer w9.45: 719.68,-1594.62 U1.14
  Top Layer w12: 719.68,-1594.62 969.32,-1844.25 969.32,-2120.85 937.72,-2152.45 870.32,-2152.45 853.32,-2169.45 853.32,-2229.45 877.32,-2253.45 953.45,-2253.45 JP1.21
P15: JP1.23 U1.15 | length 1071.6
  Top Layer w9.45: 739.37,-1560.9 U1.15
  Top Layer w12: 739.37,-1560.9 991.32,-1812.85 991.32,-2139.45 953.32,-2177.45 953.32,-2221.45 979.32,-2247.45 1047.45,-2247.45 JP1.23
P16: JP1.25 U1.16 | length 1090.3
  Top Layer w9.45: 759.06,-1542.47 U1.16
  Top Layer w12: 759.06,-1542.47 1012.32,-1795.74 1012.32,-2139.45 1026.37,-2153.5 1123.37,-2153.5 1153.32,-2183.45 1153.32,-2253.32 JP1.25
P17: JP1.27 U1.17 | length 1175.2
  Top Layer w9.45: 778.74,-1526.94 U1.17
  Top Layer w12: 778.74,-1526.94 1033.68,-1781.88 1033.68,-2125.07 1042.11,-2133.5 1217.37,-2133.5 1253.32,-2169.45 1253.32,-2222.5 1277.32,-2246.5 1287.32,-2246.5 1300,-2259.18 JP1.27
P21: JP1.29 U1.21 | length 1383.7
  Top Layer w9.45: U1.21 857.48,-1484.45 889.3,-1516.26
  Top Layer w12: 889.3,-1516.26 1037.19,-1516.26 1062.44,-1541.51 1062.44,-1755.92 1053.68,-1764.68 1053.68,-2064.45 1102.73,-2113.5 1397.37,-2113.5 1450.32,-2166.45 1450.32,-2249.68 JP1.29
P22: JP1.31 U1.22 | length 1503.9
  Top Layer w9.45: U1.22 877.17,-1405.6 v1@897.32,-1385.45
  Top Layer w12: v1@897.32,-1385.45 v1(911.18,-1385.45)
  Bottom Layer w12: v1(911.18,-1385.45) 911.18,-1700.31 986.32,-1775.45 1223.73,-1775.45 1298.73,-1850.45 1437.32,-1850.45 1547.32,-1960.45 1547.32,-2252.68 JP1.31
P23: JP1.32 U1.23 | length 1473.1
  Top Layer w9.45: U1.23 896.85,-1492.45 1053.37,-1492.45
  Top Layer w12: 1053.37,-1492.45 1086.37,-1525.45 1133.32,-1525.45 1240.81,-1630.93 1241,-1896 1197.32,-1938.45 1132.32,-1938.45 1101.32,-1969.45 1101.32,-2009.45 1116.32,-2024.45 1455.32,-2024.45 1500,-2069.13 JP1.32
P27: JP1.30 U1.27 | length 1469.6
  Top Layer w9.45: U1.27 1044.32,-1366.54 1091.23,-1413.45
  Top Layer w12: 1091.23,-1413.45 1342,-1414 1354.32,-1402.45 1416,-1402 1483,-1468 1483,-1560 1459,-1583 1321,-1583 1294,-1612 1294,-1817 v1(1380,-1902.95)
  Bottom Layer w12: v1(1380,-1902.95) 1400,-1922.95 JP1.30
P28: JP1.28 U1.28 | length 1544.1
  Top Layer w9.45: U1.28 1053.72,-1346.85 1100.32,-1393.45
  Top Layer w12: 1100.32,-1393.45 1323.32,-1393.45 1338.32,-1380.45 1436.32,-1380.45 1508,-1453 1508,-1706 1447,-1767 v1(1447.32,-1940.45)
  Bottom Layer w12: JP1.28 1347.45,-2247.45 1437.32,-2247.45 1447.32,-2237.45 v1(1447.32,-1940.45)
P30: JP1.26 U1.30 | length 2259.2
  Top Layer w9.45: U1.30 1043.89,-1307.48 1109.86,-1373.45
  Top Layer w12: 1109.86,-1373.45 1248.32,-1373.45 1267.32,-1354.45 1524,-1356 v1(1555,-1376) ; JP1.26 1253.32,-2253.32 1253.32,-2323.45 1282.32,-2353.45 1682,-2354 v1(1736,-2300)
  Bottom Layer w12: v1(1555,-1376) 1555,-1815 1736,-1996 v1(1736,-2300)
P32: JP1.24 U1.32 | length 2470.5
  Top Layer w9.45: v1(935.32,-1286.45) 953.66,-1268.11 U1.32
  Bottom Layer w12: v1(935.32,-1286.45) 971.32,-1250.45 971.32,-1174.45 957.32,-1160.45 867.32,-1160.45 817.32,-1210.45 817.32,-1839.45 740.32,-1916.45 740.32,-2028.45 687.32,-2081.45 515.32,-2081.45 453.32,-2143.45 453.32,-2229.45 477.32,-2253.45 632.32,-2253.45 653.32,-2274.45 653.32,-2323.45 677.32,-2347.45 937.32,-2347.45 953.32,-2331.45 953.32,-2270.45 976.32,-2247.45 1052.55,-2247.45 JP1.24
P34: JP1.22 U1.34 | length 2394.5
  Top Layer w9.45: U1.34 1084.32,-1228.74
  Top Layer w12: 1084.32,-1228.74 1106.03,-1250.45 1173.96,-1250.45 1178.22,-1246.19 1238.06,-1246.19 v1(1242.32,-1250.45)
  Bottom Layer w12: JP1.22 1046.5,-2153.5 1137.32,-2153.5 1149.32,-2165.5 1149.32,-2319.45 1177.32,-2347.45 1608,-2348 1659.32,-2295.45 1659.32,-1964.45 1442,-1747 1442,-1615 1424,-1596 1337.32,-1595.45 1242.32,-1500.45 v1(1242.32,-1250.45)
P35: JP1.20 U1.35 | length 1640.3
  Top Layer w9.45: U1.35 1101.7,-1209.06
  Top Layer w12: 1101.7,-1209.06 1121.09,-1228.45 1153.96,-1228.45 1156.22,-1226.19 1181.96,-1226.19 1197.26,-1210.88 1277.32,-1210.88 1286.56,-1220.12 1286.56,-1272.7 1224.81,-1334.45 v1(1126.32,-1334.45) ; v1(1125.32,-1582.45) 1082.44,-1625.33 1082.44,-1784.04 1073.68,-1792.79 1073.68,-2019.04 v1(1127.32,-2072.68)
  Bottom Layer w12: JP1.20 1027.32,-2072.68 v1(1127.32,-2072.68) ; v1(1125.32,-1582.45) 1166.32,-1541.45 1166.32,-1374.45 v1(1126.32,-1334.45)
P36: JP1.18 U1.36 | length 1682.3
  Top Layer w9.45: v1(932.32,-1203.45) 946.4,-1189.37 U1.36
  Bottom Layer w12: JP1.18 976.55,-2023.45 1178.32,-2023.45 1192.32,-2009.45 1192.32,-1833.45 1154.32,-1795.45 956.75,-1795.45 837.32,-1676.02 837.32,-1246.82 880.7,-1203.45 v1(932.32,-1203.45)
P37: JP1.16 U1.37 | length 1833
  Top Layer w9.45: U1.37 1120.32,-1169.68
  Top Layer w12: v1(1119.32,-1485.45) 1180.32,-1485.45 1268,-1573 1268,-1908 v1(1285,-1934) ; 1120.32,-1169.68 v1(1140.09,-1189.45)
  Bottom Layer w12: JP1.16 747.45,-2247.45 937.32,-2247.45 949.32,-2235.45 949.32,-2179.45 995.27,-2133.5 1144.49,-2133.5 1285,-1993 v1(1285,-1934) ; v1(1119.32,-1485.45) 1087.32,-1453.45 1087.32,-1242.21 v1(1140.09,-1189.45)
P38: JP1.14 U1.38 | length 1330
  Top Layer w9.45: 928.77,-1150 U1.38
  Top Layer w12: JP1.14 600,-2133.5 701.32,-2032.18 v1(701.32,-1922.45) ; v1(776.32,-1205.45) 873.32,-1205.45 928.77,-1150
  Bottom Layer w12: v1(701.32,-1922.45) 796.32,-1827.45 796.32,-1225.45 v1(776.32,-1205.45)
P39: JP1.12 U1.39 | length 1878.4
  Top Layer w9.45: U1.39 v1@1177.72,-1130.31
  Top Layer w12: v1(1113.32,-1843.04) 1113.32,-1666.45 v1(1133.32,-1646.45) ; v1@1177.72,-1130.31 v1(1193.32,-1145.91)
  Bottom Layer w12: JP1.12 594.98,-2105.02 733.64,-2105.02 760.32,-2078.33 760.32,-1927.95 845.24,-1843.04 v1(1113.32,-1843.04) ; v1(1133.32,-1646.45) 1082.44,-1595.56 1082.44,-1511.45 1067.32,-1496.33 1067.32,-1197.46 1118.87,-1145.91 v1(1193.32,-1145.91)
P40: JP1.10 U1.40 | length 2411.4
  Top Layer w9.45: U1.40 1145.14,-1110.63
  Top Layer w12: JP1.10 582.95,-2017.05 597.32,-2017.05 622.92,-1991.45 622.92,-1918.85 658.32,-1883.45 731.32,-1883.45 v1(800.32,-1952.45) ; 1145.14,-1110.63 1150.32,-1105.45 1226.32,-1105.45 v1(1258.32,-1137.45) ; v1(1153.32,-1892.45) 1195.32,-1850.45 v1(1195.32,-1646.45)
  Bottom Layer w12: v1(800.32,-1952.45) 860.32,-1892.45 v1(1153.32,-1892.45) ; v1(1195.32,-1646.45) 1156.32,-1685.45 1116.32,-1685.45 1062.32,-1631.45 1062.32,-1529.45 1047.32,-1514.45 1047.32,-1166.45 1109.32,-1104.45 1225.32,-1104.45 v1(1258.32,-1137.45)
P43: JP1.8 U1.43 | length 1709.4
  Top Layer w9.45: 917.72,-1091.17 957.32,-1051.58 U1.43
  Top Layer w12: v1(814.32,-1106.45) 829.6,-1091.17 917.72,-1091.17
  Bottom Layer w12: JP1.8 300,-2099.77 489.32,-1910.45 526.45,-1910.45 704.32,-1732.58 704.32,-1521.45 670.32,-1487.45 670.32,-1353.45 624.32,-1307.45 624.32,-1113.45 631.32,-1106.45 v1(814.32,-1106.45)
P44: JP1.6 U1.44 | length 1864.8
  Top Layer w9.45: 905.88,-1031.89 U1.44
  Top Layer w12: JP1.6 339.43,-2060.57 v1(439.2,-2060.57) ; v1(887.32,-1050.45) 905.88,-1031.89
  Bottom Layer w12: v1(439.2,-2060.57) 517.2,-2060.57 642.32,-1935.45 642.32,-1848.09 744.32,-1746.09 744.32,-1476.45 690.32,-1422.45 690.32,-1320.45 644.32,-1274.45 644.32,-1149.45 664.32,-1129.45 759.32,-1129.45 775.32,-1145.45 837.32,-1145.45 887.32,-1095.45 v1(887.32,-1050.45)
P47: JP2.1 U1.47 | length 1831.8
  Top Layer w9.45: 955.32,-891.24 955.32,-972.83 U1.47
  Top Layer w12: v1(910.32,-423.45) 994.32,-507.45 994.32,-579.45 1094.32,-679.45 1094.32,-729.45 1082.32,-741.45 1034.32,-741.45 1016.32,-759.45 1016.32,-830.24 955.32,-891.24
  Bottom Layer w12: JP2.1 69.45,-169.45 228.04,-169.45 304.65,-246.06 304.65,-274.35 453.75,-423.45 764.32,-423.45 783.32,-404.45 891.32,-404.45 v1(910.32,-423.45)
P49: JP2.3 U1.49 | length 2262.8
  Top Layer w9.45: U1.49 1048.31,-933.46 1071.23,-910.54
  Top Layer w12: 1071.23,-910.54 1071.23,-809.45 1096.13,-784.54 1119.23,-784.54 1134.32,-769.45 1134.32,-674.16 1275.32,-533.16 v1(1275.32,-210.45)
  Bottom Layer w12: JP2.3 133.77,-100 180.32,-53.45 237.32,-53.45 253.32,-69.45 253.32,-119.08 418.69,-284.45 546.32,-284.45 586.32,-324.45 1161.32,-324.45 v1(1275.32,-210.45)
P50: JP2.5 U1.50 | length 1600.3
  Top Layer w9.45: U1.50 1034.05,-913.78 1043.32,-904.5 1043.32,-772.45
  Top Layer w12: v1(976.32,-403.45) 1014.32,-441.45 1014.32,-569.45 1114.32,-669.45 1114.32,-749.45 1102.32,-761.45 1054.32,-761.45 1043.32,-772.45
  Bottom Layer w12: JP2.5 327.32,-227.32 327.32,-259.45 471.32,-403.45 753.32,-403.45 772.32,-384.45 957.32,-384.45 v1(976.32,-403.45)
P53: JP2.7 U1.53 | length 1403
  Top Layer w9.45: U1.53 v1@896.85,-754.92
  Top Layer w12: v1(235.32,-344.45) 300,-279.77 JP2.7 ; v1(353.32,-526.45) 353.32,-710.45 v1(395.32,-752.45) ; v1@896.85,-754.92 v1(907.32,-744.45)
  Bottom Layer w12: v1(235.32,-344.45) 235.32,-408.45 v1(353.32,-526.45) ; v1(395.32,-752.45) 433.32,-790.45 861.32,-790.45 v1(907.32,-744.45)
P54: JP2.9 U1.54 | length 1399.1
  Top Layer w9.45: 862.32,-784.6 877.17,-799.45 U1.54
  Top Layer w12: v1(827.32,-161.45) 784.32,-204.45 784.32,-304.45 787.32,-307.45 787.32,-327.45 784.32,-330.45 784.32,-594.45 862.32,-672.45 862.32,-784.6
  Bottom Layer w12: JP2.9 446.5,-146.5 529.45,-146.5 546.5,-129.45 546.5,-72.84 566.5,-52.84 839.71,-52.84 847.32,-60.45 847.32,-141.45 v1(827.32,-161.45)
P55: JP2.11 U1.55 | length 1164.9
  Top Layer w9.45: 840.77,-711.72 840.77,-794.24 857.48,-810.95 U1.55
  Top Layer w12: JP2.11 500,-137.13 549.32,-186.45 549.32,-272.45 500.41,-321.36 500.41,-390.54 560.32,-450.45 560.32,-607.45 580.32,-627.45 v1(580.32,-751.45) ; v1(820.5,-691.45) 840.77,-711.72
  Bottom Layer w12: v1(580.32,-751.45) 731.32,-751.45 791.32,-691.45 v1(820.5,-691.45)
P59: JP2.13 U1.59 | length 971.1
  Top Layer w9.45: 764.6,-324.72 764.6,-789.39 778.74,-803.53 U1.59
  Top Layer w12: JP2.13 633,-100 679.55,-53.45 737.32,-53.45 750.32,-66.45 750.32,-310.45 764.6,-324.72
P60: JP2.15 U1.60 | length 775.2
  Top Layer w9.45: 739.32,-461 739.32,-789.71 759.06,-809.45 U1.60
  Top Layer w12: JP2.15 724.32,-124.32 724.32,-446 739.32,-461
P61: JP2.17 U1.61 | length 4022.5
  Top Layer w9.45: 739.37,-918.4 U1.61
  Top Layer w12: v1(683.32,-974.45) 739.37,-918.4 ; JP2.17 849.55,-50.45 1017.32,-50.45 1047.32,-80.45 1047.32,-304.45 1061.66,-318.79 1061.66,-476.06 1122.05,-536.45 1161.32,-536.45 v1(1215.32,-482.45) ; v1(1240,-1011) 1299,-951 1534,-951 1565,-920 1835,-920 v1(1901,-853)
  Bottom Layer w12: v1(683.32,-974.45) 730.32,-927.45 1157.32,-927.45 1208.32,-876.45 1302.32,-876.45 1335.32,-909.45 1336,-1010 1327,-1011 v1(1240,-1011) ; v1(1215.32,-482.45) 1338.56,-359.21 1438.42,-359.21 1484.19,-313.45 1939.32,-313.45 1955.32,-329.45 1955,-800 v1(1901,-853)
P62: JP2.19 U1.62 | length 1067.8
  Top Layer w9.45: U1.62 719.68,-481.36
  Top Layer w12: v1(645.32,-165.45) 704.32,-224.45 704.32,-466 719.68,-481.36
  Bottom Layer w12: v1(645.32,-165.45) 685.32,-205.45 857.32,-205.45 900,-162.77 JP2.19
P63: JP2.21 U1.63 | length 1003.5
  Top Layer w9.45: U1.63 700,-504.09
  Top Layer w12: v1(665.32,-264.45) 665.32,-469.41 700,-504.09 ; v1(823.32,-264.45) 939.94,-147.83 952.17,-147.83 JP2.21
  Bottom Layer w12: v1(665.32,-264.45) v1(823.32,-264.45)
P64: JP2.23 U1.64 | length 2472.1
  Top Layer w9.45: v1(680.31,-912.45) U1.64
  Top Layer w12: JP2.23 1149.32,-50.68 1149.32,18.55 1177.32,46.55 1237.32,46.55 1253.32,30.55 1253.32,-46.5 1254.27,-47.45 1525.32,-47.45 1547.32,-69.45 1547.32,-190.45 1473,-264 1473,-568 1452,-589 1381,-589 1320,-650 v1(1279.32,-649)
  Bottom Layer w12: v1(680.31,-912.45) 692.27,-900.49 1154.28,-900.49 1198.32,-856.45 1365.32,-856.45 1392.32,-829.45 1392.32,-749.45 1382.32,-739.45 1317.77,-739.45 1279.32,-701 v1(1279.32,-649)
P65: JP2.25 U1.65 | length 1316.7
  Top Layer w9.45: U1.65 660.63,-786.45
  Top Layer w12: v1(597.32,-269.45) 633.32,-305.45 633.32,-467.29 669.48,-503.45 669.48,-777.6 660.63,-786.45
  Bottom Layer w12: v1(597.32,-269.45) 632.32,-304.45 995.55,-304.45 JP2.25
P67: JP2.27 U1.67 | length 1670.5
  Top Layer w9.45: v1(621.26,-914.45) U1.67
  Top Layer w12: JP2.27 1328.32,-128.32 1328.32,-392.45 1295.32,-425.45 1295.32,-541.45 1214.32,-622.45 1214.32,-679.45 1313.32,-778.45 v1(1353.32,-778.45)
  Bottom Layer w12: v1(621.26,-914.45) 663.26,-872.45 1145.32,-872.45 1181.32,-836.45 1295.32,-836.45 v1(1353.32,-778.45)
P68: JP2.29 U1.68 | length 1549.6
  Top Layer w9.45: U1.68 601.58,-793.42 620,-775
  Top Layer w12: v1(544.32,-344.45) 586,-386.13 586,-593 607,-614 607,-708 620,-721 620,-775
  Bottom Layer w12: v1(544.32,-344.45) 1236.32,-344.45 1400,-180.77 JP2.29
P71: JP2.31 U1.71 | length 1503.9
  Top Layer w9.45: U1.71 v1@542.52,-651.7
  Top Layer w12: v1(539.27,-648.45) v1@542.52,-651.7 ; v1(1368,-424) 1368,-232 JP2.31
  Bottom Layer w12: v1(539.27,-648.45) 664.18,-648.45 705.52,-607.1 1081.67,-607.1 1157.97,-530.8 1260,-531 v1(1368,-424)
P72: JP2.32 U1.72 | length 1780.5
  Top Layer w9.45: 501.32,-543.45 501.32,-788.45 522.83,-809.96 U1.72
  Top Layer w12: 501.32,-543.45 v1(521.32,-523.45)
  Bottom Layer w12: v1(521.32,-523.45) 731.32,-523.45 774.32,-566.45 918.32,-566.45 1075.32,-409.45 1256.89,-409.45 1327.13,-339.21 1377.32,-339.21 1567.32,-149.21 1567.32,-29.45 1537.87,0 JP2.32
P74: JP2.30 U1.74 | length 1880.5
  Top Layer w9.45: 474.32,-546.45 474.32,-794.45 483.46,-803.59 U1.74
  Top Layer w12: v1(454.32,-526.45) 474.32,-546.45
  Bottom Layer w12: v1(454.32,-526.45) 497.32,-483.45 754.32,-483.45 817.32,-546.45 904.37,-546.45 1061.37,-389.45 1248.61,-389.45 1318.84,-319.21 1356.73,-319.21 1546.5,-129.45 1546.5,-69.45 1530.55,-53.5 1453.5,-53.5 JP2.30
P75: JP2.28 U1.75 | length 1932.2
  Top Layer w9.45: 454.32,-630.56 454.32,-801.99 463.78,-811.45 U1.75
  Top Layer w12: 454.32,-630.56 415.32,-591.56 415.32,-498.74 455.32,-458.74 v1(455.32,-325.45)
  Bottom Layer w12: v1(455.32,-325.45) 513.32,-383.45 725.32,-383.45 744.32,-364.45 1245.32,-364.45 1447.32,-162.45 1447.32,-80.45 1417.32,-50.45 1350.45,-50.45 JP2.28
P79: JP2.26 U1.79 | length 2328.2
  Top Layer w9.45: U1.79 444.32,-972.83 444.32,-852.45
  Top Layer w12: v1(407.32,-443.45) 395.32,-455.45 395.32,-626.45 434.32,-665.45 434.32,-842.45 444.32,-852.45 ; v1(843.32,-443.45) 843.32,-424.45 943.32,-324.45 997.32,-324.45 1041.66,-368.79 1041.66,-538.06 1103.05,-599.45 1157.04,-599.45 1254.32,-502.16 1254.32,-287.45 1153.32,-186.45 1153.32,-77.45 1190,-40.77 1200,-40.77 JP2.26
  Bottom Layer w12: v1(407.32,-443.45) v1(843.32,-443.45)
P80: JP2.24 U1.80 | length 2031.8
  Top Layer w9.45: 331.6,-992.52 U1.80
  Top Layer w12: v1(314.32,-636.45) 314.32,-674.45 239.32,-749.45 239.32,-900.24 331.6,-992.52 ; v1(1147.32,-477.45) v1(1147.32,-257.45)
  Bottom Layer w12: v1(314.32,-636.45) 351.32,-599.45 560.32,-599.45 577.32,-616.45 651.54,-616.45 680.89,-587.1 1037.67,-587.1 v1(1147.32,-477.45) ; JP2.24 1153.5,-53.5 1230.55,-53.5 1246.5,-69.45 1246.5,-158.27 v1(1147.32,-257.45)
P81: JP2.22 U1.81 | length 1830.5
  Top Layer w9.45: 310.11,-1012.2 U1.81
  Top Layer w12: 310.11,-1012.2 219.32,-921.42 219.32,-707.26 275.32,-651.26 275.32,-471.39 414.65,-332.05 414.65,-301.12 v1(490.32,-225.45)
  Bottom Layer w12: v1(490.32,-225.45) 844.32,-225.45 863.32,-244.45 1004.61,-244.45 1046.5,-202.56 1046.5,-46.5 JP2.22
P85: JP2.20 U1.85 | length 3949.3
  Top Layer w9.45: v1(326.32,-1062.45) 354.82,-1090.94 U1.85
  Top Layer w12: v1(836.32,-501.45) 804.32,-469.45 804.32,-339.45 v1(950.32,-193.45)
  Bottom Layer w12: v1(326.32,-1062.45) 221.32,-1167.45 -121.72,-1167.45 -146.68,-1192.41 -146.68,-1258.45 -187.68,-1299.45 -402.68,-1299.45 -432.68,-1269.45 -432.68,-403.45 -303.68,-274.45 208.32,-274.45 234.82,-300.95 301.7,-300.95 368.32,-367.57 368.32,-469.45 382.32,-483.45 446.32,-483.45 466.32,-463.45 798.32,-463.45 v1(836.32,-501.45) ; JP2.20 950.32,-50.32 v1(950.32,-193.45)
P86: JP2.18 U1.86 | length 1772.4
  Top Layer w9.45: 235.32,-1110.63 U1.86
  Top Layer w12: 235.32,-1110.63 199.32,-1074.63 199.32,-696.45 255.32,-640.45 255.32,-458.9 388.32,-325.9 388.32,-277.95 453.32,-212.95 453.32,-69.45 475.32,-47.45 537.32,-47.45 553.32,-31.45 553.32,22.55 577.32,46.55 753.45,46.55 JP2.18
P87: JP2.16 U1.87 | length 1720.4
  Top Layer w9.45: 197.19,-1130.31 U1.87
  Top Layer w12: 197.19,-1130.31 179.32,-1112.45 179.32,-687.45 193.32,-673.45 193.32,-482.45 367.32,-308.45 367.32,-220.45 v1(401.32,-186.45) ; v1(586.32,-165.45) 553.32,-132.45 553.32,-78.45 580.32,-51.45 648.55,-51.45 JP2.16
  Bottom Layer w12: v1(401.32,-186.45) 565.32,-186.45 v1(586.32,-165.45)
P88: JP2.14 U1.88 | length 1748.7
  Top Layer w9.45: 182.32,-1150 U1.88
  Top Layer w12: 182.32,-1150 159.32,-1127 159.32,-640.45 173.32,-626.45 173.32,-473.22 347.32,-299.22 v1(347.32,-47.45)
  Bottom Layer w12: v1(347.32,-47.45) 433.5,-47.45 453.32,-27.63 453.32,22.55 477.32,46.55 553.45,46.55 JP2.14
P89: JP2.12 U1.89 | length 2968.9
  Top Layer w9.45: U1.89 456.09,-1169.68 v1(475.32,-1150.45)
  Top Layer w12: v1(-163.68,-523.45) -163.68,-34.45 -82.68,46.55 453.45,46.55 JP2.12
  Bottom Layer w12: v1(-163.68,-523.45) -205.19,-523.45 -338.88,-657.13 -338.88,-719.45 -300.68,-757.65 -300.68,-1169.45 -270.68,-1199.45 -229.31,-1199.45 -177.31,-1147.45 91.5,-1147.45 225.5,-1013.45 338.32,-1013.45 v1(475.32,-1150.45)
P90: JP2.10 U1.90 | length 2095.7
  Top Layer w9.45: 191.44,-1189.37 U1.90
  Top Layer w12: v1(153.32,-215.45) 153.32,-597.45 139.32,-611.45 139.32,-1137.25 191.44,-1189.37
  Bottom Layer w12: v1(153.32,-215.45) -22.68,-215.45 -46.68,-191.45 -46.68,-59.45 -35.68,-48.45 139.1,-48.45 147.32,-40.22 147.32,16.55 177.32,46.55 353.45,46.55 JP2.10
P91: JP2.8 U1.91 | length 3099.9
  Top Layer w9.45: U1.91 v1@476.93,-1209.06
  Top Layer w12: v1(247.32,-251.45) 247.32,-52.68 JP2.8 ; v1@476.93,-1209.06 v1(477.32,-1209.45)
  Bottom Layer w12: v1(247.32,-251.45) 244.32,-254.45 -389.68,-254.45 -452.68,-317.45 -452.68,-1289.45 -422.68,-1319.45 -141.68,-1319.45 -126.68,-1304.45 -126.68,-1207.45 -121.68,-1202.45 470.32,-1202.45 v1(477.32,-1209.45)
P92: JP2.6 U1.92 | length 1556.7
  Top Layer w9.45: 176.81,-1228.74 U1.92
  Top Layer w12: 176.81,-1228.74 119.32,-1171.25 119.32,-591.73 131.72,-579.33 131.72,-326.86 75.32,-270.46 75.32,-210.18 146.5,-139 146.5,-53.5 JP2.6
P96: JP2.4 U1.96 | length 1603.9
  Top Layer w9.45: 176.35,-1307.48 U1.96
  Top Layer w12: JP2.4 53.32,-46.68 53.32,-341.45 101.32,-389.45 101.32,-568.45 99.32,-570.45 99.32,-1230.45 176.35,-1307.48
P97: JP2.2 U1.97 | length 2016.9
  Top Layer w9.45: 166.04,-1327.16 U1.97
  Top Layer w12: JP2.2 -111.66,-111.66 -111.66,-577.43 -242.68,-708.45 -242.68,-761.45 -135.68,-868.45 -135.68,-933.45 -80.68,-988.45 -80.68,-1121.7 -126.68,-1167.7 -126.68,-1285.45 -119.68,-1292.45 131.32,-1292.45 166.04,-1327.16
pads on no net: JP3.6 JP3.7 JP3.8 U2.2 U2.9 U2.12 U2.13 U2.14 U2.15 U2.16

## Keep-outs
Keep-Out Layer:
  lines w10: -500,-2400 -500,100 2000,100 2000,-2400 -500,-2400

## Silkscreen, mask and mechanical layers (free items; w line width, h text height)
Bottom Overlay:
  lines w10: 1100,-420 1230.55,-420 1260,-449.45 1260,-580 1300,-620 1320,-620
